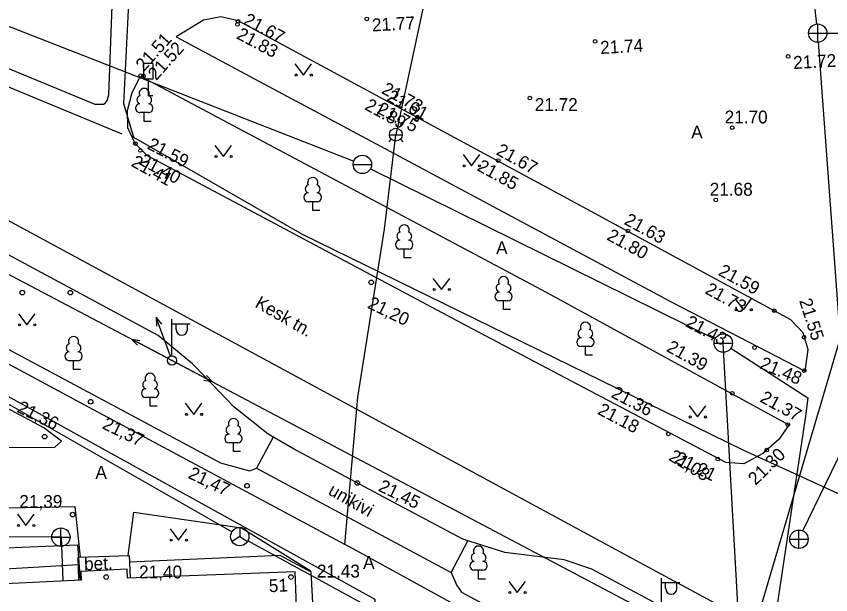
# Model space of a CAD drawing. Extents: x 714038 to 714279, y 6589845 to 6590041.
# Drawn here: x 714116.25 to 714160.6, y 6589955.67 to 6589987.15 of the extents above; entities that cross this region are included whole.
import ezdxf

# ---------------------------------------------------------------- set-up
doc = ezdxf.new("R2010")
doc.units = 0
for name, color, linetype in [('HALJASTUS', 7, 'Continuous'), ('HOONE', 7, 'Continuous'), ('HOONEDET', 7, 'Continuous'), ('KKAEV', 7, 'Continuous'), ('KORGUS', 7, 'Continuous'), ('KTRASS', 7, 'Continuous'), ('LIIKLUS', 7, 'Continuous'), ('MPKAABEL', 7, 'Continuous'), ('MPOHULIIN', 7, 'Continuous'), ('POST', 7, 'Continuous'), ('PUU', 7, 'Continuous'), ('SIKAEV', 7, 'Continuous'), ('SITRASS', 7, 'Continuous'), ('SKKAEV', 7, 'Continuous'), ('SKTRASS', 7, 'Continuous'), ('TEE', 7, 'Continuous'), ('VKAEV', 7, 'Continuous'), ('VTRASS', 7, 'Continuous'), ('Слой 1', 7, 'Continuous')]:
    doc.layers.add(name, color=color, linetype=linetype)

msp = doc.modelspace()

# ---------------------------------------------------------------- linework, layer by layer
at = {"layer": 'HALJASTUS'}
for p, q in [((714131.424, 6589984.561), (714131.887, 6589983.955)), ((714131.887, 6589983.955), (714132.333, 6589984.561)), ((714127.062, 6589980.122), (714127.526, 6589979.515)), ((714127.526, 6589979.515), (714127.971, 6589980.122)), ((714140.579, 6589979.625), (714141.042, 6589979.018)), ((714141.042, 6589979.018), (714141.488, 6589979.625)), ((714138.94, 6589972.883), (714139.403, 6589972.276)), ((714139.403, 6589972.276), (714139.849, 6589972.883)), ((714155.382, 6589971.789), (714155.846, 6589971.182)), ((714155.846, 6589971.182), (714156.291, 6589971.789)), ((714116.366, 6589970.961), (714116.829, 6589970.354)), ((714116.829, 6589970.354), (714117.275, 6589970.961)), ((714125.45, 6589966.091), (714125.913, 6589965.484)), ((714125.913, 6589965.484), (714126.359, 6589966.091)), ((714152.886, 6589965.948), (714153.35, 6589965.341)), ((714153.35, 6589965.341), (714153.795, 6589965.948)), ((714116.312, 6589960.046), (714116.775, 6589959.439)), ((714116.775, 6589959.439), (714117.221, 6589960.046)), ((714124.621, 6589959.245), (714125.084, 6589958.638)), ((714125.084, 6589958.638), (714125.53, 6589959.245)), ((714143.067, 6589956.393), (714143.53, 6589955.786)), ((714143.53, 6589955.786), (714143.976, 6589956.393))]:
    msp.add_line(p, q, dxfattribs=at)
for centre, radius in [((714131.486, 6589983.955), 0.055), ((714132.315, 6589983.955), 0.055), ((714127.125, 6589979.515), 0.055), ((714127.953, 6589979.515), 0.055), ((714140.641, 6589979.018), 0.055), ((714141.47, 6589979.018), 0.055), ((714139.002, 6589972.276), 0.055), ((714139.831, 6589972.276), 0.055), ((714116.575, 6589972.114), 0.125), ((714155.445, 6589971.182), 0.055), ((714156.273, 6589971.182), 0.055), ((714116.428, 6589970.354), 0.055), ((714117.257, 6589970.354), 0.055), ((714125.512, 6589965.484), 0.055), ((714126.341, 6589965.484), 0.055), ((714152.948, 6589965.341), 0.055), ((714153.777, 6589965.341), 0.055), ((714116.374, 6589959.439), 0.055), ((714117.203, 6589959.439), 0.055), ((714124.683, 6589958.638), 0.055), ((714125.512, 6589958.638), 0.055), ((714143.129, 6589955.786), 0.055), ((714143.958, 6589955.786), 0.055)]:
    msp.add_circle(centre, radius, dxfattribs=at)
at = {"layer": 'HOONE'}
for points in [[(714037.81, 6590017.576), (714059.08, 6590006.51), (714072.38, 6589999.69), (714082.14, 6589994.37), (714104.85, 6589981.96), (714150.21, 6589957.43), (714183.55, 6589939.45), (714202.68, 6589928.99), (714214.04, 6589922.75), (714222.92, 6589918.06), (714237.47, 6589910.29), (714252.27, 6589902.23), (714256.602, 6589899.815), (714258.577, 6589898.715), (714261.69, 6589896.98)], [(714079.4, 6589956.78), (714092.78, 6589957.29), (714111.868, 6589958.066), (714112.653, 6589958.098), (714119.58, 6589958.38), (714119.728, 6589956.461)], [(714119.783, 6589956.463), (714090.49, 6589955.04), (714090.9, 6589944.49), (714131.853, 6589946.089), (714131.432, 6589956.918), (714122.304, 6589956.561), (714122.284, 6589957.061), (714119.765, 6589956.935), (714119.783, 6589956.463)]]:
    msp.add_lwpolyline(points, dxfattribs=at)
at = {"layer": 'HOONEDET'}
for points in [[(714122.407, 6589957.455), (714130.601, 6589957.826), (714132.296, 6589956.921), (714132.905, 6589945.462), (714122.63, 6589944.95)], [(714102.25, 6589956.39), (714107.94, 6589956.63), (714119.63, 6589957.314)]]:
    msp.add_lwpolyline(points, dxfattribs=at)
at = {"layer": 'KKAEV'}
for p, q in [((714118.676, 6589958.302), (714118.676, 6589959.302)), ((714158.865, 6589958.188), (714158.865, 6589959.188)), ((714118.176, 6589958.802), (714119.176, 6589958.802)), ((714158.365, 6589958.688), (714159.365, 6589958.688))]:
    msp.add_line(p, q, dxfattribs=at)
for centre in [(714118.676, 6589958.802), (714158.865, 6589958.688)]:
    msp.add_circle(centre, 0.5, dxfattribs=at)
at = {"layer": 'KORGUS'}
for centre, radius in [((714128.33, 6589986.876), 0.1), ((714135.337, 6589987.01), 0.1), ((714128.291, 6589986.709), 0.1), ((714147.765, 6589985.783), 0.1), ((714158.277, 6589984.963), 0.1), ((714123.024, 6589983.922), 0.1), ((714123.173, 6589983.896), 0.1), ((714144.22, 6589982.698), 0.1), ((714138.038, 6589981.532), 0.1), ((714138.092, 6589981.665), 0.1), ((714155.238, 6589981.089), 0.1), ((714122.738, 6589980.22), 0.1), ((714123.003, 6589979.852), 0.1), ((714142.493, 6589979.297), 0.1), ((714154.34, 6589977.158), 0.1), ((714149.553, 6589975.472), 0.1), ((714135.58, 6589972.67), 0.125), ((714119.19, 6589972.11), 0.125), ((714157.52, 6589971.128), 0.1), ((714159.144, 6589969.681), 0.1), ((714156.455, 6589969.123), 0.1), ((714159.152, 6589967.865), 0.1), ((714155.234, 6589966.635), 0.1), ((714120.3, 6589966.17), 0.125), ((714158.264, 6589964.93), 0.1), ((714117.79, 6589964.27), 0.125), ((714151.762, 6589964.417), 0.1), ((714157.117, 6589963.538), 0.1), ((714154.445, 6589963.051), 0.1), ((714128.81, 6589961.6), 0.125), ((714134.82, 6589961.75), 0.125), ((714119.32, 6589960.03), 0.125), ((714121.14, 6589956.63), 0.125), ((714131.21, 6589956.63), 0.125)]:
    msp.add_circle(centre, radius, dxfattribs=at)
at = {"layer": 'KTRASS'}
for points in [[(714118.684, 6589958.815), (714099.241, 6589958.769), (714080.742, 6589963.482)], [(714118.684, 6589958.815), (714118.781, 6589956.421)]]:
    msp.add_lwpolyline(points, dxfattribs=at)
at = {"layer": 'LIIKLUS'}
for points in [[(714123.179, 6589984.573), (714123.179, 6589983.723)], [(714123.679, 6589984.573), (714123.179, 6589984.573)], [(714123.679, 6589984.573), (714123.679, 6589983.723)], [(714123.679, 6589983.723), (714123.179, 6589983.723)], [(714123.429, 6589983.723), (714123.429, 6589982.823)], [(714123.679, 6589982.823), (714123.429, 6589982.823)]]:
    msp.add_lwpolyline(points, dxfattribs=at)
at = {"layer": 'MPKAABEL'}
for points in [[(714037.81, 6590016.164), (714045.98, 6590012.32), (714093.89, 6589992.4), (714122, 6589980.75)], [(714123.717, 6589997.796), (714122.485, 6589997.244), (714122.51, 6589991.06), (714122.373, 6589988.225), (714122.093, 6589982.401), (714122.625, 6589980.577), (714131.807, 6589975.295), (714155.806, 6589963.558), (714167.836, 6589958.048), (714177.51, 6589953.25), (714191.113, 6589945.528), (714192.794, 6589944.261), (714190.81, 6589933.623), (714190.196, 6589929.064), (714190.863, 6589919.753), (714192.278, 6589911.176), (714192.96, 6589897.79), (714194.31, 6589864.41), (714194.86, 6589849.85), (714194.551, 6589845.18)], [(714124.725, 6589968.419), (714097.597, 6589982.691), (714097.447, 6589982.821)], [(714151.383, 6589954.327), (714124.725, 6589968.419)]]:
    msp.add_lwpolyline(points, dxfattribs=at)
at = {"layer": 'MPOHULIIN'}
for p, q in [((714123.861, 6589970.765), (714123.876, 6589970.289)), ((714123.861, 6589970.765), (714124.157, 6589970.392)), ((714124.638, 6589968.653), (714123.861, 6589970.765)), ((714122.514, 6589969.586), (714122.843, 6589969.242)), ((714122.514, 6589969.586), (714122.983, 6589969.506)), ((714124.504, 6589968.535), (714122.514, 6589969.586)), ((714124.946, 6589968.302), (714126.935, 6589967.25)), ((714126.935, 6589967.25), (714126.606, 6589967.594)), ((714126.935, 6589967.25), (714126.466, 6589967.33))]:
    msp.add_line(p, q, dxfattribs=at)
at = {"layer": 'POST'}
for p, q in [((714124.725, 6589968.669), (714124.725, 6589970.669)), ((714124.725, 6589970.419), (714125.725, 6589970.419)), ((714124.951, 6589970.098), (714124.951, 6589970.419)), ((714125.564, 6589970.098), (714125.564, 6589970.419)), ((714151.383, 6589954.577), (714151.383, 6589956.577)), ((714151.383, 6589956.327), (714152.383, 6589956.327)), ((714151.61, 6589956.006), (714151.61, 6589956.327)), ((714152.223, 6589956.006), (714152.223, 6589956.327))]:
    msp.add_line(p, q, dxfattribs=at)
for radius in [0.25, 0.0234]:
    msp.add_circle((714124.725, 6589968.419), radius, dxfattribs=at)
for centre in [(714125.258, 6589970.098), (714151.917, 6589956.006)]:
    msp.add_arc(centre, 0.306, 180, 0, dxfattribs=at)
at = {"layer": 'PUU'}
for p, q in [((714123.456, 6589981.906), (714122.976, 6589981.906)), ((714123.216, 6589981.431), (714123.216, 6589981.906)), ((714123.596, 6589981.431), (714123.216, 6589981.431)), ((714132.629, 6589977.06), (714132.149, 6589977.06)), ((714132.389, 6589976.585), (714132.389, 6589977.06)), ((714132.769, 6589976.585), (714132.389, 6589976.585)), ((714137.616, 6589974.483), (714137.136, 6589974.483)), ((714137.376, 6589974.008), (714137.376, 6589974.483)), ((714137.756, 6589974.008), (714137.376, 6589974.008)), ((714143.023, 6589971.661), (714142.543, 6589971.661)), ((714142.783, 6589971.186), (714142.783, 6589971.661)), ((714143.163, 6589971.186), (714142.783, 6589971.186)), ((714147.481, 6589969.179), (714147.001, 6589969.179)), ((714147.241, 6589968.704), (714147.241, 6589969.179)), ((714119.608, 6589968.406), (714119.128, 6589968.406)), ((714119.368, 6589967.931), (714119.368, 6589968.406)), ((714147.621, 6589968.704), (714147.241, 6589968.704)), ((714119.748, 6589967.931), (714119.368, 6589967.931)), ((714123.775, 6589966.4), (714123.295, 6589966.4)), ((714123.535, 6589965.925), (714123.535, 6589966.4)), ((714123.915, 6589965.925), (714123.535, 6589965.925)), ((714128.313, 6589963.936), (714127.833, 6589963.936)), ((714128.073, 6589963.461), (714128.073, 6589963.936)), ((714128.453, 6589963.461), (714128.073, 6589963.461)), ((714141.662, 6589956.997), (714141.182, 6589956.997)), ((714141.422, 6589956.522), (714141.422, 6589956.997)), ((714141.802, 6589956.522), (714141.422, 6589956.522))]:
    msp.add_line(p, q, dxfattribs=at)
for centre, radius, start, end in [((714123.216, 6589982.951), 0.277, 332.5799, 207.4201), ((714123.046, 6589982.603), 0.233, 109.0217, 253.1415), ((714123.386, 6589982.603), 0.233, 286.8508, 70.9859), ((714122.978, 6589982.143), 0.238, 90.0016, 269.3953), ((714123.453, 6589982.143), 0.238, 270.6047, 89.9984), ((714132.389, 6589978.105), 0.277, 332.5799, 207.4201), ((714132.219, 6589977.757), 0.233, 109.0217, 253.1415), ((714132.559, 6589977.757), 0.233, 286.8508, 70.9859), ((714132.151, 6589977.297), 0.238, 90.0016, 269.3953), ((714132.626, 6589977.297), 0.238, 270.6047, 89.9984), ((714137.206, 6589975.181), 0.233, 109.0217, 253.1415), ((714137.376, 6589975.528), 0.277, 332.5799, 207.4201), ((714137.546, 6589975.181), 0.233, 286.8508, 70.9859), ((714137.138, 6589974.721), 0.238, 90.0016, 269.3953), ((714137.613, 6589974.721), 0.238, 270.6047, 89.9984), ((714142.783, 6589972.706), 0.277, 332.5799, 207.4201), ((714142.612, 6589972.358), 0.233, 109.0217, 253.1415), ((714142.953, 6589972.358), 0.233, 286.8508, 70.9859), ((714142.545, 6589971.898), 0.238, 90.0016, 269.3953), ((714143.02, 6589971.898), 0.238, 270.6047, 89.9984), ((714147.241, 6589970.224), 0.277, 332.5799, 207.4201), ((714147.071, 6589969.877), 0.233, 109.0217, 253.1415), ((714147.411, 6589969.877), 0.233, 286.8508, 70.9859), ((714119.368, 6589969.451), 0.277, 332.5799, 207.4201), ((714147.003, 6589969.417), 0.238, 90.0016, 269.3953), ((714147.478, 6589969.417), 0.238, 270.6047, 89.9984), ((714119.198, 6589969.104), 0.233, 109.0217, 253.1415), ((714119.538, 6589969.104), 0.233, 286.8508, 70.9859), ((714119.131, 6589968.644), 0.238, 90.0016, 269.3953), ((714119.606, 6589968.644), 0.238, 270.6047, 89.9984), ((714123.535, 6589967.445), 0.277, 332.5799, 207.4201), ((714123.365, 6589967.097), 0.233, 109.0217, 253.1415), ((714123.705, 6589967.097), 0.233, 286.8508, 70.9859), ((714123.298, 6589966.637), 0.238, 90.0016, 269.3953), ((714123.773, 6589966.637), 0.238, 270.6047, 89.9984), ((714128.073, 6589964.981), 0.277, 332.5799, 207.4201), ((714127.903, 6589964.634), 0.233, 109.0217, 253.1415), ((714128.243, 6589964.634), 0.233, 286.8508, 70.9859), ((714127.835, 6589964.174), 0.238, 90.0016, 269.3953), ((714128.31, 6589964.174), 0.238, 270.6047, 89.9984), ((714141.422, 6589958.042), 0.277, 332.5799, 207.4201), ((714141.252, 6589957.695), 0.233, 109.0217, 253.1415), ((714141.592, 6589957.695), 0.233, 286.8508, 70.9859), ((714141.184, 6589957.235), 0.238, 90.0016, 269.3953), ((714141.659, 6589957.235), 0.238, 270.6047, 89.9984)]:
    msp.add_arc(centre, radius, start, end, dxfattribs=at)
at = {"layer": 'SIKAEV'}
for p, q in [((714128.42, 6589959.334), (714128.42, 6589958.834)), ((714128.42, 6589958.834), (714128.005, 6589958.559)), ((714128.42, 6589958.834), (714128.835, 6589958.559))]:
    msp.add_line(p, q, dxfattribs=at)
msp.add_circle((714128.42, 6589958.834), 0.5, dxfattribs=at)
at = {"layer": 'SITRASS'}
for points in [[(714037.81, 6590017.083), (714041.45, 6590015.4), (714049.64, 6590011.61), (714053.69, 6590009.84), (714078.46, 6589999.77), (714120.53, 6589982.37), (714120.99, 6589982.37), (714121.09, 6589982.42), (714121.19, 6589982.57), (714121.29, 6589982.87), (714121.49, 6589988.215), (714121.85, 6589997.82), (714121.9, 6589998.22), (714123.574, 6590001.009)], [(714127.986, 6589959.082), (714115.909, 6589965.994), (714078.842, 6589985.253)], [(714173.493, 6589934.191), (714170.111, 6589936.05), (714128.857, 6589958.592)]]:
    msp.add_lwpolyline(points, dxfattribs=at)
at = {"layer": 'SKKAEV'}
for p, q in [((714159.89, 6589985.734), (714159.89, 6589986.734)), ((714159.39, 6589986.234), (714160.39, 6589986.234))]:
    msp.add_line(p, q, dxfattribs=at)
msp.add_circle((714159.89, 6589986.234), 0.5, dxfattribs=at)
at = {"layer": 'SKTRASS'}
for points in [[(714159.249, 6589991.792), (714159.833, 6589986.731)], [(714160.39, 6589986.234), (714168.601, 6589986.237)], [(714159.92, 6589985.735), (714161.475, 6589964.649)], [(714159.079, 6589959.14), (714161.293, 6589963.7)]]:
    msp.add_lwpolyline(points, dxfattribs=at)
at = {"layer": 'TEE'}
for points in [[(714159.213, 6589967.827), (714159.372, 6589969.018), (714159.101, 6589969.925), (714158.434, 6589970.635), (714146.041, 6589977.347), (714128.337, 6589986.899), (714127.393, 6589987.118), (714126.442, 6589986.948), (714124.953, 6589986.041)], [(714124.953, 6589986.041), (714131.491, 6589982.524)], [(714151.459, 6589971.853), (714131.491, 6589982.524)], [(714117.751, 6589964.757), (714096.936, 6589975.889), (714086.792, 6589981.374), (714085.763, 6589981.428), (714086.329, 6589971.355), (714087.167, 6589969.326), (714088.497, 6589967.804), (714090.737, 6589966.182), (714091.388, 6589965.99), (714102.223, 6589966.405), (714103.211, 6589966.21), (714105.25, 6589963.96), (714106.305, 6589963.671), (714118.34, 6589963.691)], [(714139.925, 6589956.876), (714140.234, 6589956.163), (714140.484, 6589955.802), (714153.095, 6589949.039), (714155.555, 6589948.306), (714154.686, 6589950.968), (714153.587, 6589953.135), (714152.58, 6589954.383), (714147.598, 6589957.067), (714146.079, 6589957.558), (714142.852, 6589957.966), (714140.567, 6589958.688), (714136.498, 6589960.842), (714131.349, 6589963.609), (714129.959, 6589964.408), (714128.087, 6589965.9), (714126.521, 6589967.542), (714125.843, 6589968.233), (714123.973, 6589969.784), (714113.651, 6589975.327)], [(714108.053, 6589973.169), (714127.373, 6589962.843), (714128.95, 6589962.409)], [(714151.459, 6589971.853), (714159.213, 6589967.827)], [(714118.34, 6589963.691), (714118.719, 6589964.018), (714117.751, 6589964.757)], [(714130.241, 6589964.246), (714129.325, 6589962.556), (714139.925, 6589956.876), (714140.841, 6589958.602)], [(714128.95, 6589962.409), (714129.325, 6589962.556)], [(714102.23, 6589956.99), (714102.2, 6589957.75), (714102.318, 6589960.133), (714119.441, 6589960.466), (714119.719, 6589957.714)], [(714122.339, 6589957.803), (714122.648, 6589960.163), (714128.51, 6589959.316), (714132.199, 6589957.028), (714132.296, 6589956.921)], [(714119.663, 6589956.458), (714119.614, 6589957.71), (714122.394, 6589957.805), (714122.442, 6589956.567)]]:
    msp.add_lwpolyline(points, dxfattribs=at)
msp.add_lwpolyline([(714122.31, 6589982.021), (714122.563, 6589983.01), (714123.006, 6589983.898), (714145.095, 6589972.133), (714158.31, 6589964.918), (714157.794, 6589964.134), (714156.908, 6589963.357), (714155.874, 6589962.798), (714154.884, 6589962.873), (714141.101, 6589970.125), (714123.399, 6589979.549), (714122.721, 6589980.223), (714122.32, 6589981.074)], close=True, dxfattribs=at)
at = {"layer": 'VKAEV'}
for p, q in [((714136.567, 6589980.705), (714137.267, 6589980.705)), ((714136.67, 6589980.458), (714136.53, 6589980.318)), ((714137.164, 6589980.458), (714137.304, 6589980.318)), ((714134.599, 6589979.088), (714135.599, 6589979.088)), ((714154.245, 6589969.365), (714155.245, 6589969.365))]:
    msp.add_line(p, q, dxfattribs=at)
for centre, radius in [((714136.917, 6589980.705), 0.35), ((714135.099, 6589979.088), 0.5), ((714154.745, 6589969.365), 0.5)]:
    msp.add_circle(centre, radius, dxfattribs=at)
at = {"layer": 'VTRASS'}
for points in [[(714166.254, 6590040.965), (714165.506, 6590022.329), (714165.378, 6590008.723), (714165.284, 6589998.807), (714165.141, 6589983.322), (714160.198, 6589966.563), (714155.909, 6589952.01), (714153.798, 6589949.498)], [(714153.798, 6589949.498), (714152.517, 6589948.338), (714134.349, 6589958.294), (714134.144, 6589958.409), (714120.209, 6589965.86), (714104.085, 6589974.529), (714097.438, 6589978.146), (714096.95, 6589978.424), (714085.013, 6589984.641), (714084.705, 6589984.858), (714077.379, 6589988.763), (714061.877, 6589996.73), (714043.432, 6590006.628), (714037.81, 6590009.751)], [(714133.719, 6589996.129), (714138.897, 6589989.951), (714136.917, 6589980.705)], [(714102.729, 6589991.799), (714114.744, 6589987.033), (714134.634, 6589979.269)], [(714134.144, 6589958.409), (714134.846, 6589966.42), (714136.3, 6589975.564), (714136.917, 6589980.705)], [(714135.542, 6589978.855), (714154.297, 6589969.586)], [(714155.959, 6589947.68), (714154.745, 6589969.365)], [(714155.165, 6589969.094), (714159.358, 6589966.391)], [(714159.358, 6589966.391), (714159.218, 6589965.381), (714156.312, 6589946.059)]]:
    msp.add_lwpolyline(points, dxfattribs=at)
at = {"layer": 'Слой 1'}
msp.add_lwpolyline([(714086, 6589982.93), (714135.78, 6589955.43), (714136.17, 6589942.13), (714118.41, 6589940.84), (714087.46, 6589939.06)], close=True, dxfattribs=at)

# ---------------------------------------------------------------- texts
at = {"layer": 'HOONE'}
msp.add_text('51', height=0.7, rotation=2.582, dxfattribs=at).set_placement((714130.013, 6589955.802))
at = {"layer": 'HOONEDET'}
msp.add_text('bet.', height=0.7, rotation=2.3189, dxfattribs=at).set_placement((714119.952, 6589956.988))
at = {"layer": 'KORGUS'}
for s, rotation, p in [(' 21.67', 331.9065, (714128.33, 6589986.876)), (' 21.77', 3.1005, (714135.375, 6589986.311)), (' 21.83', 331.9065, (714127.961, 6589986.091)), (' 21.51', 48.1468, (714123.024, 6589983.922)), (' 21.52', 48.1468, (714123.694, 6589983.429)), (' 21.74', 3.1005, (714147.803, 6589985.084)), (' 21.72', 3.1005, (714158.315, 6589984.264)), (' 21.73', 331.476, (714135.865, 6589983.115)), (' 21.61', 331.9065, (714136.147, 6589982.703)), (' 21.89', 331.476, (714134.943, 6589982.231)), (' 21.75', 331.9065, (714135.609, 6589982.035)), (' 21.59', 332.7299, (714123.098, 6589980.085)), (' 21.67', 331.2665, (714142.103, 6589979.781)), (' 21.41 ', 331.1014, (714122.225, 6589979.151)), (' 21.40', 331.6543, (714122.671, 6589979.236)), (' 21.85', 331.2665, (714141.063, 6589978.916)), (' 21.63 ', 331.4292, (714149.072, 6589975.987)), (' 21.80 ', 331.4292, (714148.126, 6589975.14)), (' 21.59', 331.2847, (714154.202, 6589973.218)), (' 21.73', 331.2847, (714153.481, 6589972.219)), ('21,20', 334.0139, (714135.327, 6589971.303)), (' 21.55 ', 287.7568, (714158.793, 6589971.922)), (' 21.43', 332.0493, (714152.409, 6589970.421)), (' 21.39', 330.7749, (714151.38, 6589969.077)), (' 21.48', 336.5655, (714156.444, 6589968.112)), (' 21.36', 332.3307, (714148.361, 6589966.563)), (' 21.37', 331.3954, (714156.469, 6589966.321)), ('21,36', 334.0139, (714116.235, 6589965.635)), (' 21.18', 332.3307, (714147.626, 6589965.643)), ('21,37', 334.0139, (714120.877, 6589964.739)), ('21,08', 329.136, (714151.729, 6589963.02)), (' 21.21', 333.1245, (714151.82, 6589963.004)), (' 21.30', 44.1521, (714156.322, 6589961.409)), ('21,47', 334.0139, (714125.555, 6589962.044)), ('21,45', 334.0139, (714135.915, 6589961.344))]:
    msp.add_text(s, height=0.7, rotation=rotation, dxfattribs=at).set_placement(p)
for s, p in [(' 21.72', (714144.22, 6589981.998)), (' 21.70', (714154.562, 6589981.318)), (' 21.68', (714153.749, 6589977.387)), ('21,39', (714116.414, 6589960.395)), ('21,40', (714122.934, 6589956.555)), ('21,43', (714132.619, 6589956.605))]:
    msp.add_text(s, height=0.7, dxfattribs=at).set_placement(p)
at = {"layer": 'TEE'}
for p in [(714153.002, 6589980.502), (714142.376, 6589974.206), (714120.558, 6589961.974), (714135.134, 6589957.072)]:
    msp.add_text('A', height=0.7, dxfattribs=at).set_placement(p)
for s, rotation, p in [('Kesk tn.', 330.0588, (714129.196, 6589971.357)), ('unikivi', 330.5024, (714133.18, 6589961.154))]:
    msp.add_text(s, height=0.7, rotation=rotation, dxfattribs=at).set_placement(p)

doc.saveas('drawing.dxf')
